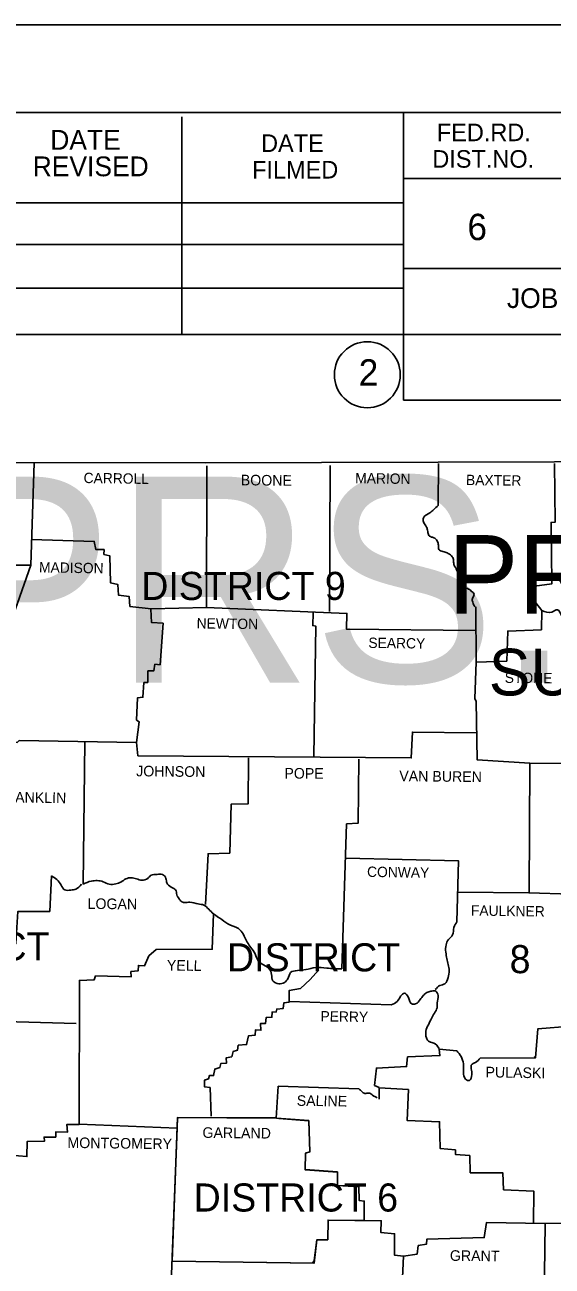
# Model space of a CAD drawing. Extents: x 1369885 to 1370219, y 379980 to 380218.
# Drawn here: x 1370154 to 1370177.5, y 380162.7 to 380217.9 of the extents above; entities that cross this region are included whole.
import ezdxf

# ---------------------------------------------------------------- set-up
doc = ezdxf.new("R2010")
doc.units = 0
for name, color, linetype in [('Default', 7, 'Continuous'), ('Level 2', 7, 'Continuous'), ('R_Draft', 7, 'Continuous'), ('R_No Plot', 7, 'Continuous'), ('STAMP_PE_FOSTER-SIGNATURE', 7, 'Continuous'), ('STAMP_PE_TAEGTMEYER', 7, 'Continuous')]:
    doc.layers.add(name, color=color, linetype=linetype)

msp = doc.modelspace()

# ---------------------------------------------------------------- linework, layer by layer
at = {"layer": 'Default'}
for points in [[(1370144.335, 380198.452), (1370162.058, 380198.442), (1370177.609, 380198.482), (1370195.96, 380198.761), (1370204.458, 380198.96)], [(1370154.458, 380198.446), (1370154.297, 380193.899)], [(1370154.338, 380195.038), (1370157.126, 380194.945), (1370157.196, 380194.596), (1370157.565, 380194.586), (1370157.555, 380194.367), (1370157.824, 380194.307), (1370157.844, 380193.112), (1370158.182, 380193.032), (1370158.202, 380192.564), (1370158.68, 380192.494), (1370158.71, 380192.056), (1370159.657, 380191.956), (1370162.118, 380192.016), (1370162.137, 380198.312)], [(1370167.627, 380198.332), (1370167.597, 380191.827)], [(1370172.449, 380198.412), (1370172.429, 380196.539)], [(1370177.609, 380198.412), (1370177.629, 380195.802), (1370177.45, 380195.792), (1370177.48, 380193.062), (1370176.713, 380192.952), (1370176.772, 380192.215), (1370177.041, 380191.876), (1370177.021, 380191.02), (1370175.527, 380190.96), (1370175.477, 380189.625), (1370174.112, 380189.575), (1370174.053, 380187.961), (1370174.122, 380187.822), (1370174.162, 380185.241), (1370176.503, 380185.082), (1370176.473, 380179.314), (1370178.336, 380179.254), (1370178.336, 380173.386), (1370176.862, 380173.277), (1370176.752, 380171.981), (1370174.292, 380171.972)], [(1370145.161, 380191.827), (1370147.254, 380191.817), (1370147.313, 380192.534), (1370148.061, 380192.534), (1370148.13, 380193.71), (1370152.404, 380193.56), (1370152.534, 380193.889), (1370154.297, 380193.899), (1370153.41, 380191.358), (1370153.241, 380187.294), (1370153.102, 380187.274), (1370153.042, 380186.048), (1370153.689, 380185.999), (1370153.789, 380186.098), (1370159.009, 380185.999), (1370159.069, 380185.411)], [(1370159.637, 380191.936), (1370159.677, 380191.339), (1370160.185, 380191.309), (1370160.055, 380189.466), (1370159.826, 380189.485), (1370159.776, 380189.187), (1370159.517, 380189.187), (1370159.507, 380188.679), (1370159.338, 380188.669), (1370159.288, 380188.021), (1370159.049, 380187.991), (1370159.009, 380187.005), (1370159.119, 380186.925), (1370159.009, 380185.999)], [(1370162.118, 380192.016), (1370168.364, 380191.747), (1370168.354, 380191.04), (1370174.082, 380190.99)], [(1370166.86, 380191.777), (1370166.85, 380191.209), (1370166.989, 380191.179), (1370166.899, 380185.391)], [(1370174.112, 380189.575), (1370174.102, 380192.046)], [(1370159.069, 380185.411), (1370171.233, 380185.321), (1370171.283, 380186.467), (1370174.112, 380186.437)], [(1370156.708, 380186.038), (1370156.638, 380179.712)], [(1370163.99, 380185.331), (1370163.98, 380183.279), (1370163.223, 380183.269), (1370163.154, 380181.087), (1370162.187, 380181.057), (1370162.078, 380178.796)], [(1370168.902, 380185.271), (1370168.872, 380182.422), (1370168.354, 380182.382), (1370168.145, 380175.937)], [(1370176.503, 380185.082), (1370182.132, 380185.052), (1370182.62, 380185.281), (1370182.59, 380180.998), (1370182.252, 380180.858), (1370181.963, 380180.599), (1370181.863, 380180.509), (1370181.853, 380179.274), (1370178.267, 380179.274)], [(1370168.324, 380180.858), (1370173.335, 380180.738), (1370173.265, 380178.029)], [(1370155.224, 380180.071), (1370155.144, 380178.497), (1370153.719, 380178.487), (1370153.639, 380177.062), (1370152.225, 380177.092), (1370152.185, 380175.628), (1370150.711, 380175.618), (1370150.661, 380174.153), (1370151.597, 380174.094), (1370151.557, 380173.645), (1370156.319, 380173.516)], [(1370173.285, 380179.354), (1370176.473, 380179.314)], [(1370162.426, 380178.387), (1370162.377, 380176.813), (1370159.876, 380176.803), (1370159.547, 380176.514), (1370159.368, 380176.076), (1370159.089, 380176.096), (1370159.079, 380175.847), (1370158.76, 380175.817), (1370158.77, 380175.588), (1370157.186, 380175.628), (1370157.126, 380175.458), (1370156.469, 380175.428), (1370156.449, 380169.023), (1370155.901, 380169.013), (1370155.941, 380168.684), (1370155.423, 380168.694), (1370155.413, 380168.455), (1370154.895, 380168.455), (1370154.905, 380168.275), (1370154.138, 380168.256), (1370154.128, 380167.588), (1370153.38, 380167.648)], [(1370167.119, 380175.897), (1370166.73, 380175.468), (1370166.302, 380175.06), (1370165.804, 380174.98), (1370165.804, 380174.462), (1370165.565, 380174.432), (1370165.525, 380174.173), (1370165.246, 380174.153), (1370165.226, 380174.024), (1370165.037, 380174.014), (1370165.027, 380173.785), (1370164.768, 380173.775), (1370164.748, 380173.516), (1370164.528, 380173.516), (1370164.538, 380173.207), (1370164.299, 380173.227), (1370164.279, 380172.988), (1370163.99, 380172.968), (1370163.901, 380172.569), (1370163.532, 380172.539), (1370163.492, 380172.32), (1370163.303, 380172.26), (1370163.243, 380172.031), (1370162.994, 380171.981), (1370163.014, 380171.752), (1370162.765, 380171.732), (1370162.715, 380171.553), (1370162.486, 380171.483), (1370162.436, 380171.194), (1370162.257, 380171.204), (1370162.207, 380171.045), (1370162.038, 380170.995), (1370162.028, 380170.696), (1370162.277, 380170.656), (1370162.327, 380169.381)], [(1370170.337, 380174.333), (1370165.814, 380174.482)], [(1370173.256, 380172.29), (1370172.468, 380172.37), (1370172.508, 380172.081), (1370171.064, 380172.021), (1370171.024, 380171.593), (1370169.679, 380171.523), (1370169.599, 380170.756), (1370169.799, 380170.656), (1370169.799, 380170.148)], [(1370176.703, 380171.991), (1370176.752, 380172.041)], [(1370168.902, 380170.607), (1370165.315, 380170.716), (1370165.216, 380169.302), (1370160.832, 380169.331), (1370160.812, 380168.853)], [(1370169.799, 380170.652), (1370171.104, 380170.567), (1370171.054, 380169.192), (1370172.488, 380169.142), (1370172.518, 380167.947), (1370173.196, 380167.887), (1370173.196, 380167.688), (1370173.833, 380167.638), (1370173.853, 380166.871), (1370175.298, 380166.871), (1370175.338, 380166.114), (1370176.683, 380166.054), (1370176.673, 380164.629)], [(1370160.814, 380168.858), (1370156.45, 380169.027)], [(1370160.593, 380162.946), (1370160.832, 380169.331), (1370165.216, 380169.312)], [(1370160.832, 380169.272), (1370160.892, 380169.331)], [(1370165.046, 380169.312), (1370166.67, 380169.192), (1370166.72, 380167.807), (1370166.531, 380167.747), (1370166.511, 380167.01), (1370167.946, 380166.911), (1370167.946, 380166.303), (1370168.902, 380166.253), (1370168.912, 380165.645), (1370169.141, 380165.615), (1370169.131, 380164.749)], [(1370165.345, 380169.282), (1370166.67, 380169.182), (1370166.72, 380167.807), (1370166.531, 380167.737), (1370166.511, 380167), (1370167.946, 380166.901), (1370167.946, 380166.303), (1370168.902, 380166.243), (1370168.912, 380165.645), (1370169.141, 380165.615), (1370169.131, 380164.799)], [(1370160.812, 380168.853), (1370160.551, 380161.977)], [(1370189.743, 380165.884), (1370185.599, 380165.994), (1370185.579, 380164.649), (1370177.191, 380164.619)], [(1370160.588, 380162.936), (1370166.899, 380162.846), (1370167.029, 380163.892), (1370167.517, 380163.892), (1370167.527, 380164.769), (1370169.898, 380164.739), (1370169.878, 380164.211), (1370170.486, 380164.161), (1370170.486, 380163.205), (1370170.884, 380163.165)], [(1370169.131, 380164.749), (1370167.527, 380164.769), (1370167.517, 380163.892), (1370167.029, 380163.892), (1370166.909, 380162.856), (1370160.593, 380162.946)], [(1370170.884, 380163.165), (1370171.492, 380163.254), (1370171.542, 380163.633), (1370171.901, 380163.693), (1370171.921, 380163.912), (1370174.481, 380163.992), (1370174.571, 380164.659), (1370177.191, 380164.619)], [(1370177.191, 380164.589), (1370177.131, 380160.166), (1370176.872, 380160.156), (1370176.842, 380157.406)], [(1370166.82, 380162.856), (1370166.919, 380162.965)], [(1370170.884, 380163.165), (1370170.755, 380160.296), (1370170.655, 380160.325), (1370170.665, 380158.851)]]:
    msp.add_lwpolyline(points, dxfattribs=at)
for points in [[(1370172.429, 380196.539), (1370172.229, 380196.37), (1370172.05, 380196.22), (1370171.791, 380196.031), (1370171.761, 380195.861), (1370171.851, 380195.682), (1370171.931, 380195.543), (1370171.97, 380195.343), (1370172.04, 380195.184), (1370172.229, 380195.114), (1370172.379, 380194.975), (1370172.439, 380194.776), (1370172.459, 380194.586), (1370172.638, 380194.497), (1370172.827, 380194.437), (1370173.016, 380194.307), (1370173.106, 380194.138), (1370173.126, 380193.929), (1370173.206, 380193.769), (1370173.295, 380193.57), (1370173.315, 380193.401), (1370173.295, 380193.241), (1370173.335, 380193.082), (1370173.475, 380192.932), (1370173.734, 380192.853), (1370173.903, 380192.743), (1370174.023, 380192.594), (1370173.953, 380192.404), (1370173.963, 380192.245), (1370174.062, 380192.046)], [(1370177.041, 380191.876), (1370177.48, 380191.807), (1370177.739, 380191.906), (1370177.928, 380191.617), (1370178.028, 380191.398), (1370178.187, 380191.079), (1370178.456, 380190.98), (1370178.655, 380190.811), (1370178.655, 380190.621), (1370178.476, 380190.442), (1370178.346, 380190.273), (1370178.386, 380190.063), (1370178.436, 380189.774), (1370178.436, 380189.505), (1370178.366, 380189.246), (1370178.306, 380189.017), (1370178.366, 380188.828), (1370178.575, 380188.858), (1370178.795, 380189.017), (1370179.024, 380189.017), (1370179.243, 380188.898), (1370179.472, 380188.689), (1370179.701, 380188.738), (1370179.891, 380188.788), (1370180.15, 380188.868), (1370180.339, 380188.768), (1370180.498, 380188.639), (1370180.697, 380188.429), (1370180.887, 380188.3), (1370181.126, 380188.18), (1370181.425, 380188.101), (1370181.694, 380187.911), (1370181.744, 380187.593), (1370181.734, 380187.324), (1370181.714, 380186.985), (1370181.684, 380186.606), (1370181.724, 380186.248), (1370181.843, 380186.009), (1370181.993, 380185.72), (1370182.032, 380185.461), (1370182.022, 380185.042)], [(1370155.224, 380180.071), (1370155.463, 380179.912), (1370155.652, 380179.663), (1370155.811, 380179.453), (1370156.09, 380179.443), (1370156.309, 380179.483), (1370156.558, 380179.702)], [(1370156.638, 380179.712), (1370156.997, 380179.842), (1370157.256, 380179.862), (1370157.525, 380179.812), (1370157.794, 380179.702), (1370158.093, 380179.722), (1370158.312, 380179.802), (1370158.531, 380179.941), (1370158.77, 380179.991), (1370158.999, 380179.941), (1370159.238, 380179.882), (1370159.507, 380179.961), (1370159.657, 380180.101), (1370159.926, 380180.141), (1370160.155, 380180.141), (1370160.314, 380179.961), (1370160.354, 380179.762), (1370160.553, 380179.573), (1370160.743, 380179.453), (1370160.802, 380179.224), (1370160.902, 380179.055), (1370160.992, 380178.945), (1370161.141, 380178.885), (1370161.38, 380178.905), (1370161.749, 380178.826), (1370161.998, 380178.776), (1370162.217, 380178.587), (1370162.426, 380178.387)], [(1370162.426, 380178.387), (1370162.805, 380178.128), (1370163.164, 380177.899), (1370163.542, 380177.73), (1370163.751, 380177.491), (1370163.931, 380177.122), (1370164.09, 380176.893), (1370164.279, 380176.604), (1370164.429, 380176.285), (1370164.658, 380176.116), (1370164.897, 380175.956), (1370165.017, 380175.688), (1370165.076, 380175.409), (1370165.335, 380175.279), (1370165.584, 380175.329), (1370165.734, 380175.498), (1370165.863, 380175.777), (1370166.162, 380175.867), (1370166.541, 380175.907), (1370166.979, 380175.996), (1370167.467, 380175.976), (1370168.145, 380175.937)], [(1370173.265, 380178.029), (1370173.126, 380177.78), (1370173.066, 380177.451), (1370172.887, 380177.242), (1370172.777, 380177.003), (1370172.767, 380176.684), (1370172.817, 380176.395), (1370172.877, 380176.126), (1370172.917, 380175.867), (1370172.867, 380175.548), (1370172.728, 380175.279), (1370172.508, 380175.199), (1370172.299, 380175.02)], [(1370170.337, 380174.333), (1370170.606, 380174.492), (1370170.755, 380174.721), (1370170.924, 380174.861), (1370171.104, 380174.661), (1370171.253, 380174.382), (1370171.422, 380174.382), (1370171.632, 380174.582), (1370171.761, 380174.751), (1370171.921, 380174.881), (1370172.1, 380174.94), (1370172.289, 380174.96), (1370172.429, 380174.751), (1370172.379, 380174.422), (1370172.379, 380174.203), (1370172.259, 380173.974), (1370172.13, 380173.735), (1370171.99, 380173.456), (1370171.881, 380173.167), (1370171.901, 380172.878), (1370172.05, 380172.689), (1370172.229, 380172.639), (1370172.468, 380172.4)], [(1370173.256, 380172.29), (1370173.445, 380172.041), (1370173.554, 380171.712), (1370173.554, 380171.344), (1370173.644, 380171.035), (1370173.823, 380170.975), (1370173.923, 380171.234), (1370173.903, 380171.493), (1370173.903, 380171.653), (1370174.092, 380171.782), (1370174.292, 380171.972)], [(1370169.719, 380170.208), (1370169.51, 380170.318), (1370169.35, 380170.417), (1370169.171, 380170.397), (1370169.031, 380170.487), (1370168.902, 380170.607)]]:
    msp.add_spline(points, degree=3, dxfattribs=at)
at = {"layer": 'R_Draft'}
msp.add_line((1370168.354, 380182.359), (1370168.379, 380182.384), dxfattribs=at)
at = {"layer": 'R_No Plot'}
msp.add_line((1369885.407, 380217.922), (1370218.741, 380217.922), dxfattribs=at)
msp.add_lwpolyline([(1369885.401, 380217.922), (1370218.741, 380217.922), (1370218.741, 380004.585), (1369885.401, 380004.585)], close=True, dxfattribs=at)
at = {"layer": 'STAMP_PE_FOSTER-SIGNATURE'}
for p, q in [((1369897.808, 380214.028), (1370213.988, 380214.028)), ((1370161.028, 380204.148), (1370161.028, 380213.828)), ((1370170.888, 380214.028), (1370170.888, 380201.228)), ((1370213.988, 380211.088), (1370170.888, 380211.088)), ((1370131.728, 380210.008), (1370170.888, 380210.008)), ((1370131.728, 380208.148), (1370170.888, 380208.148)), ((1370213.988, 380207.088), (1370170.888, 380207.088)), ((1370173.848, 380207.088), (1370213.988, 380207.088)), ((1370131.728, 380206.208), (1370170.888, 380206.208)), ((1370213.988, 380204.148), (1370131.728, 380204.148)), ((1370170.888, 380201.228), (1370213.988, 380201.228))]:
    msp.add_line(p, q, dxfattribs=at)
msp.add_circle((1370169.275, 380202.363), 1.467, dxfattribs=at)

# ---------------------------------------------------------------- texts
at = {"layer": 'Default'}
for s, height, rotation, p in [('CARROLL', 0.4603, 359.1481, (1370156.648, 380197.545)), ('BOONE', 0.4713, 359.4001, (1370163.642, 380197.445)), ('MARION', 0.4603, 359.1854, (1370168.733, 380197.535)), ('BAXTER', 0.4603, 359.2559, (1370173.664, 380197.455)), ('MADISON', 0.4603, 359.0906, (1370154.666, 380193.57)), ('NEWTON', 0.4603, 359.2717, (1370161.679, 380191.079)), ('SEARCY', 0.4601, 359.2527, (1370169.32, 380190.213)), ('STONE', 0.4601, 359.4001, (1370175.387, 380188.659)), ('JOHNSON', 0.4713, 359.3514, (1370158.989, 380184.504)), ('POPE', 0.4713, 359.6155, (1370165.584, 380184.405)), ('VAN BUREN', 0.4713, 359.3508, (1370170.695, 380184.285)), ('FRANKLIN', 0.4713, 359.1815, (1370152.763, 380183.349)), ('CONWAY', 0.4601, 359.0371, (1370169.261, 380180.031)), ('LOGAN', 0.4713, 359.3969, (1370156.827, 380178.607)), ('FAULKNER', 0.4603, 359.2486, (1370173.883, 380178.308)), ('YELL', 0.4713, 359.1987, (1370160.354, 380175.867)), ('PERRY', 0.4603, 359.0858, (1370167.188, 380173.605)), ('PULASKI', 0.4713, 359.053, (1370174.531, 380171.115)), ('SALINE', 0.4713, 359.1491, (1370166.132, 380169.85)), ('MONTGOMERY', 0.4713, 359.2944, (1370155.931, 380167.977)), ('GARLAND', 0.4713, 359.3658, (1370161.938, 380168.425)), ('GRANT', 0.4713, 359.4032, (1370172.947, 380162.956))]:
    msp.add_text(s, height=height, rotation=rotation, dxfattribs=at).set_placement(p)
for s, height, p in [('DISTRICT 9', 1.2493, (1370159.218, 380192.345)), ('DISTRICT', 1.2493, (1370147.433, 380176.315)), ('DISTRICT', 1.2493, (1370163.034, 380175.827)), ('8', 1.249, (1370175.607, 380175.747)), ('DISTRICT 6', 1.2493, (1370161.547, 380165.147))]:
    msp.add_text(s, height=height, dxfattribs=at).set_placement(p)
at = {"layer": 'Level 2'}
msp.add_text('SPENCER CREEK STR. & APPRS. (S)', height=9.16, dxfattribs=at).set_placement((1369982.371, 380188.67))
at = {"layer": 'STAMP_PE_FOSTER-SIGNATURE'}
for s, height, p in [('DATE', 0.8792, (1370155.168, 380212.368)), ('FED.RD.', 0.7819, (1370172.368, 380212.748)), ('DATE', 0.7819, (1370164.548, 380212.268)), ('REVISED', 0.8792, (1370154.388, 380211.188)), ('DIST.NO.', 0.7819, (1370172.168, 380211.568)), ('FILMED', 0.7819, (1370164.148, 380211.088)), ('6', 1.172, (1370173.728, 380208.348)), ('JOB NO.', 0.8792, (1370175.488, 380205.328)), ('2', 1.172, (1370168.892, 380201.877))]:
    msp.add_text(s, height=height, dxfattribs=at).set_placement(p)
at = {"layer": 'STAMP_PE_TAEGTMEYER'}
for s, height, p in [('PRELIMINARY', 3.5, (1370172.871, 380191.728)), ('SUBJECT TO REVISION', 2.07511, (1370174.68, 380188.099))]:
    msp.add_text(s, height=height, dxfattribs=at).set_placement(p)

doc.saveas('drawing.dxf')
